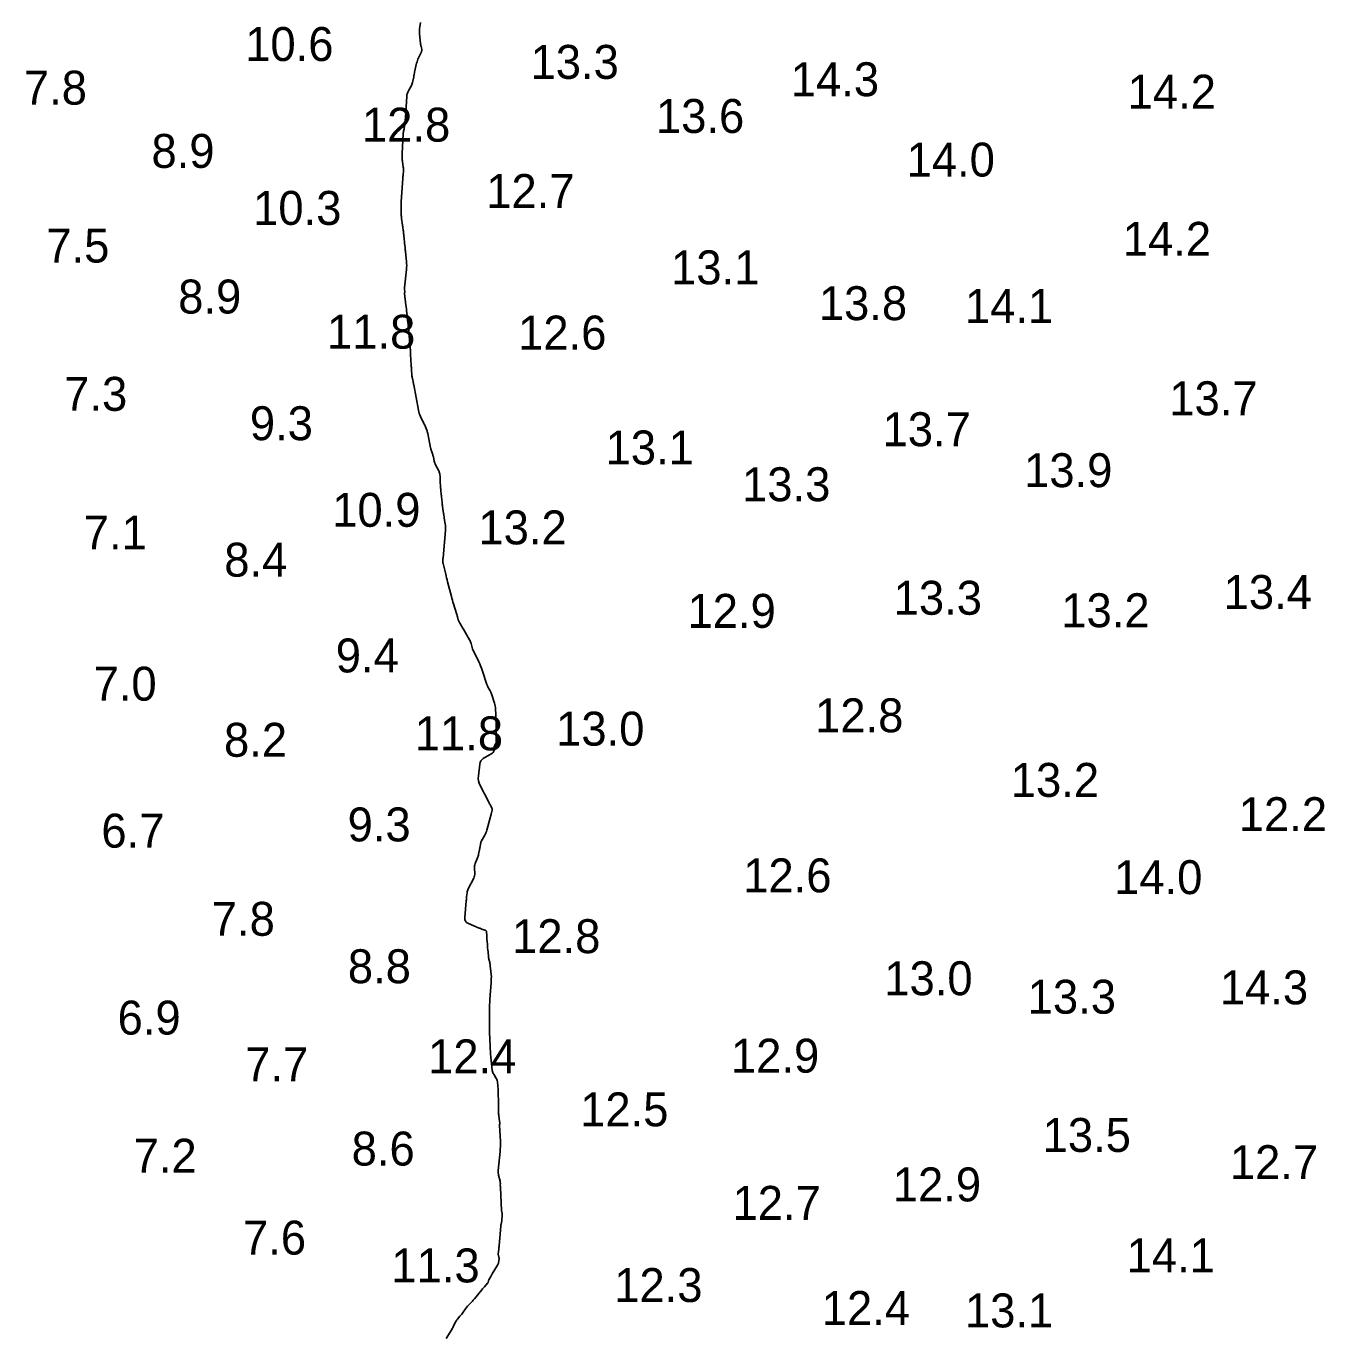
# Model space of a CAD drawing. Extents: x 815352 to 820877, y 582403 to 597439.
# Drawn here: x 820452.6 to 820644, y 590619.8 to 590813 of the extents above; entities that cross this region are included whole.
import ezdxf

# ---------------------------------------------------------------- set-up
doc = ezdxf.new("R2010")
doc.units = 0
doc.layers.add('V-CONT-EL12', color=7, linetype='Continuous')
doc.layers.add('V-TOPO-SOUN', color=7, linetype='Continuous')

msp = doc.modelspace()

# ---------------------------------------------------------------- linework, layer by layer
at = {"layer": 'V-CONT-EL12'}
msp.add_lwpolyline([(820514.49, 590619.55), (820515.32, 590620.92), (820515.39, 590621.05), (820515.46, 590621.17), (820515.53, 590621.3), (820515.59, 590621.44), (820515.85, 590621.98), (820515.91, 590622.1), (820515.99, 590622.22), (820516.07, 590622.33), (820516.15, 590622.44), (820516.52, 590622.86), (820516.62, 590622.97), (820516.7, 590623.07), (820516.79, 590623.18), (820516.87, 590623.3), (820517.43, 590624.08), (820517.53, 590624.2), (820517.62, 590624.32), (820517.73, 590624.44), (820517.83, 590624.54), (820518.27, 590624.98), (820518.38, 590625.08), (820518.48, 590625.2), (820518.58, 590625.31), (820518.68, 590625.43), (820519.76, 590626.76), (820519.85, 590626.87), (820519.94, 590626.97), (820520.03, 590627.07), (820520.12, 590627.17), (820520.6, 590627.71), (820520.63, 590627.74), (820520.65, 590627.78), (820520.67, 590627.83), (820520.68, 590627.87), (820520.73, 590628.06), (820520.74, 590628.1), (820520.76, 590628.15), (820520.77, 590628.19), (820520.79, 590628.23), (820521.05, 590628.72), (820521.1, 590628.81), (820521.15, 590628.91), (820521.2, 590629), (820521.26, 590629.09), (820522.07, 590630.39), (820522.12, 590630.49), (820522.16, 590630.58), (820522.19, 590630.69), (820522.21, 590630.79), (820522.28, 590631.31), (820522.28, 590631.37), (820522.28, 590631.43), (820522.27, 590631.49), (820522.26, 590631.55), (820522.19, 590631.79), (820522.18, 590631.85), (820522.17, 590631.91), (820522.17, 590631.97), (820522.17, 590632.03), (820522.24, 590632.73), (820522.26, 590632.87), (820522.27, 590633), (820522.28, 590633.14), (820522.29, 590633.28), (820522.52, 590636.12), (820522.53, 590636.19), (820522.54, 590636.26), (820522.55, 590636.33), (820522.57, 590636.4), (820522.64, 590636.69), (820522.66, 590636.76), (820522.68, 590636.83), (820522.69, 590636.9), (820522.69, 590636.98), (820522.75, 590637.79), (820522.75, 590637.85), (820522.75, 590637.9), (820522.74, 590637.95), (820522.73, 590638.01), (820522.68, 590638.22), (820522.67, 590638.27), (820522.66, 590638.33), (820522.65, 590638.38), (820522.65, 590638.43), (820522.47, 590641.82), (820522.47, 590641.9), (820522.47, 590641.98), (820522.46, 590642.05), (820522.46, 590642.13), (820522.47, 590642.44), (820522.46, 590642.52), (820522.46, 590642.59), (820522.45, 590642.67), (820522.43, 590642.75), (820522.22, 590643.63), (820522.19, 590643.81), (820522.17, 590643.98), (820522.16, 590644.16), (820522.17, 590644.33), (820522.43, 590647.11), (820522.46, 590647.5), (820522.47, 590647.89), (820522.48, 590648.28), (820522.47, 590648.67), (820522.37, 590650.96), (820522.37, 590650.99), (820522.37, 590651.02), (820522.37, 590651.05), (820522.37, 590651.08), (820522.38, 590651.19), (820522.38, 590651.22), (820522.38, 590651.25), (820522.38, 590651.28), (820522.38, 590651.31), (820522.25, 590652.35), (820522.23, 590652.48), (820522.22, 590652.62), (820522.22, 590652.76), (820522.21, 590652.9), (820522.22, 590653.45), (820522.22, 590653.58), (820522.22, 590653.72), (820522.21, 590653.86), (820522.21, 590654), (820522.14, 590656.17), (820522.14, 590656.32), (820522.13, 590656.48), (820522.11, 590656.64), (820522.1, 590656.79), (820522.03, 590657.42), (820522, 590657.57), (820521.96, 590657.72), (820521.9, 590657.86), (820521.82, 590657.99), (820521.49, 590658.51), (820521.41, 590658.65), (820521.35, 590658.79), (820521.31, 590658.93), (820521.28, 590659.09), (820521.07, 590661.09), (820521.03, 590661.47), (820521, 590661.86), (820520.98, 590662.25), (820520.96, 590662.63), (820520.89, 590664.74), (820520.88, 590665.14), (820520.87, 590665.54), (820520.86, 590665.94), (820520.86, 590666.34), (820520.87, 590667.93), (820520.87, 590668.33), (820520.89, 590668.73), (820520.91, 590669.13), (820520.93, 590669.53), (820521.13, 590672.04), (820521.13, 590672.11), (820521.13, 590672.17), (820521.13, 590672.23), (820521.13, 590672.29), (820521.11, 590672.64), (820521.11, 590672.66), (820521.11, 590672.67), (820521.12, 590672.69), (820521.12, 590672.7), (820521.14, 590672.76), (820521.15, 590672.77), (820521.15, 590672.79), (820521.15, 590672.8), (820521.15, 590672.82), (820520.98, 590674.49), (820520.97, 590674.61), (820520.95, 590674.74), (820520.93, 590674.86), (820520.9, 590674.98), (820520.79, 590675.46), (820520.77, 590675.59), (820520.75, 590675.71), (820520.73, 590675.83), (820520.72, 590675.95), (820520.62, 590676.9), (820520.6, 590677.08), (820520.59, 590677.27), (820520.57, 590677.45), (820520.56, 590677.63), (820520.5, 590678.48), (820520.49, 590678.61), (820520.48, 590678.73), (820520.47, 590678.85), (820520.46, 590678.97), (820520.43, 590679.48), (820520.41, 590679.58), (820520.36, 590679.66), (820520.29, 590679.73), (820520.19, 590679.77), (820519.76, 590679.9), (820519.65, 590679.94), (820519.54, 590679.98), (820519.44, 590680.02), (820519.33, 590680.06), (820517.76, 590680.72), (820517.5, 590680.86), (820517.32, 590681.06), (820517.23, 590681.31), (820517.22, 590681.61), (820517.45, 590684.08), (820517.46, 590684.23), (820517.47, 590684.38), (820517.49, 590684.53), (820517.5, 590684.67), (820517.57, 590685.27), (820517.59, 590685.41), (820517.62, 590685.56), (820517.67, 590685.69), (820517.73, 590685.83), (820518.54, 590687.43), (820518.61, 590687.59), (820518.66, 590687.76), (820518.69, 590687.94), (820518.69, 590688.12), (820518.66, 590688.85), (820518.66, 590689.03), (820518.68, 590689.21), (820518.72, 590689.39), (820518.78, 590689.56), (820519.11, 590690.39), (820519.16, 590690.53), (820519.2, 590690.67), (820519.24, 590690.8), (820519.27, 590690.95), (820519.4, 590691.57), (820519.42, 590691.68), (820519.44, 590691.8), (820519.46, 590691.91), (820519.48, 590692.02), (820519.55, 590692.48), (820519.58, 590692.59), (820519.61, 590692.7), (820519.65, 590692.8), (820519.7, 590692.9), (820520.18, 590693.75), (820520.27, 590693.93), (820520.35, 590694.11), (820520.42, 590694.3), (820520.48, 590694.49), (820520.96, 590696.3), (820520.97, 590696.32), (820520.97, 590696.34), (820520.98, 590696.35), (820520.98, 590696.37), (820521, 590696.44), (820521.01, 590696.45), (820521.01, 590696.47), (820521.02, 590696.49), (820521.02, 590696.5), (820521.11, 590696.8), (820521.12, 590696.86), (820521.14, 590696.92), (820521.15, 590696.97), (820521.17, 590697.03), (820521.27, 590697.42), (820521.28, 590697.5), (820521.28, 590697.58), (820521.26, 590697.66), (820521.23, 590697.74), (820520.95, 590698.26), (820520.89, 590698.37), (820520.83, 590698.49), (820520.78, 590698.6), (820520.72, 590698.71), (820519.49, 590701.07), (820519.35, 590701.41), (820519.25, 590701.76), (820519.22, 590702.12), (820519.23, 590702.49), (820519.43, 590704.22), (820519.48, 590704.47), (820519.59, 590704.69), (820519.74, 590704.87), (820519.95, 590705.03), (820521.23, 590705.79), (820521.27, 590705.82), (820521.32, 590705.85), (820521.36, 590705.89), (820521.39, 590705.94), (820521.53, 590706.12), (820521.56, 590706.17), (820521.58, 590706.22), (820521.59, 590706.27), (820521.59, 590706.33), (820521.57, 590706.77), (820521.58, 590706.83), (820521.59, 590706.9), (820521.61, 590706.96), (820521.64, 590707.02), (820521.8, 590707.25), (820521.83, 590707.31), (820521.85, 590707.37), (820521.87, 590707.44), (820521.87, 590707.5), (820521.84, 590710.69), (820521.84, 590710.9), (820521.83, 590711.11), (820521.83, 590711.32), (820521.81, 590711.53), (820521.76, 590712.36), (820521.75, 590712.57), (820521.71, 590712.77), (820521.67, 590712.98), (820521.61, 590713.18), (820521.16, 590714.55), (820521.11, 590714.67), (820521.06, 590714.8), (820521.01, 590714.91), (820520.95, 590715.03), (820520.69, 590715.49), (820520.63, 590715.61), (820520.57, 590715.73), (820520.52, 590715.85), (820520.48, 590715.97), (820519.79, 590718.06), (820519.68, 590718.37), (820519.56, 590718.68), (820519.43, 590718.99), (820519.29, 590719.29), (820518.55, 590720.8), (820518.49, 590720.94), (820518.43, 590721.08), (820518.38, 590721.23), (820518.34, 590721.38), (820518.17, 590721.97), (820518.12, 590722.11), (820518.07, 590722.25), (820518, 590722.39), (820517.93, 590722.53), (820517.08, 590724.01), (820517, 590724.14), (820516.93, 590724.26), (820516.86, 590724.39), (820516.78, 590724.52), (820516.45, 590725.07), (820516.4, 590725.17), (820516.35, 590725.28), (820516.31, 590725.39), (820516.28, 590725.5), (820516.15, 590725.94), (820516.12, 590726.05), (820516.09, 590726.17), (820516.05, 590726.28), (820516.02, 590726.39), (820515.57, 590727.82), (820515.48, 590728.1), (820515.4, 590728.37), (820515.32, 590728.65), (820515.25, 590728.93), (820514.7, 590731.08), (820514.63, 590731.37), (820514.56, 590731.65), (820514.49, 590731.94), (820514.42, 590732.22), (820514.03, 590733.8), (820514.02, 590733.86), (820514.01, 590733.93), (820514, 590734), (820514, 590734.07), (820514.01, 590734.35), (820514.02, 590734.42), (820514.02, 590734.49), (820514.03, 590734.56), (820514.03, 590734.63), (820514.37, 590738.65), (820514.37, 590738.7), (820514.38, 590738.76), (820514.38, 590738.81), (820514.39, 590738.86), (820514.4, 590739.09), (820514.4, 590739.13), (820514.4, 590739.18), (820514.4, 590739.22), (820514.4, 590739.26), (820514.37, 590739.43), (820514.37, 590739.47), (820514.36, 590739.51), (820514.36, 590739.55), (820514.35, 590739.59), (820514.21, 590740.5), (820514.19, 590740.67), (820514.16, 590740.83), (820514.14, 590741), (820514.11, 590741.16), (820513.97, 590742.16), (820513.94, 590742.33), (820513.92, 590742.49), (820513.9, 590742.65), (820513.88, 590742.82), (820513.8, 590743.59), (820513.79, 590743.7), (820513.78, 590743.81), (820513.76, 590743.92), (820513.75, 590744.03), (820513.71, 590744.46), (820513.7, 590744.57), (820513.69, 590744.68), (820513.68, 590744.79), (820513.67, 590744.9), (820513.61, 590746.04), (820513.61, 590746.16), (820513.6, 590746.28), (820513.59, 590746.4), (820513.58, 590746.52), (820513.53, 590746.99), (820513.51, 590747.11), (820513.48, 590747.23), (820513.44, 590747.34), (820513.4, 590747.44), (820512.94, 590748.33), (820512.88, 590748.46), (820512.83, 590748.59), (820512.78, 590748.73), (820512.74, 590748.87), (820512.6, 590749.49), (820512.57, 590749.61), (820512.54, 590749.72), (820512.51, 590749.83), (820512.47, 590749.94), (820512.32, 590750.39), (820512.28, 590750.5), (820512.25, 590750.61), (820512.22, 590750.72), (820512.2, 590750.84), (820511.77, 590752.94), (820511.74, 590753.07), (820511.71, 590753.2), (820511.67, 590753.32), (820511.62, 590753.44), (820511.42, 590753.93), (820511.37, 590754.05), (820511.32, 590754.17), (820511.26, 590754.29), (820511.21, 590754.41), (820510.7, 590755.46), (820510.6, 590755.68), (820510.52, 590755.9), (820510.45, 590756.13), (820510.4, 590756.36), (820509.7, 590760.11), (820509.68, 590760.23), (820509.66, 590760.35), (820509.63, 590760.47), (820509.61, 590760.59), (820509.51, 590761.06), (820509.48, 590761.18), (820509.46, 590761.3), (820509.45, 590761.42), (820509.44, 590761.55), (820509.38, 590762.31), (820509.37, 590762.48), (820509.36, 590762.65), (820509.35, 590762.82), (820509.34, 590762.99), (820509.25, 590764.59), (820509.25, 590764.67), (820509.24, 590764.74), (820509.24, 590764.81), (820509.23, 590764.89), (820509.22, 590765.19), (820509.21, 590765.26), (820509.21, 590765.34), (820509.2, 590765.41), (820509.2, 590765.49), (820509.17, 590765.83), (820509.17, 590765.91), (820509.16, 590765.99), (820509.15, 590766.07), (820509.15, 590766.15), (820508.93, 590768.54), (820508.92, 590768.6), (820508.92, 590768.65), (820508.91, 590768.71), (820508.91, 590768.76), (820508.89, 590768.98), (820508.88, 590769.04), (820508.87, 590769.09), (820508.87, 590769.15), (820508.86, 590769.21), (820508.68, 590770.76), (820508.65, 590771.03), (820508.62, 590771.31), (820508.59, 590771.59), (820508.56, 590771.86), (820508.37, 590773.55), (820508.36, 590773.57), (820508.36, 590773.6), (820508.37, 590773.62), (820508.37, 590773.65), (820508.38, 590773.75), (820508.39, 590773.78), (820508.39, 590773.8), (820508.39, 590773.83), (820508.39, 590773.85), (820508.36, 590774.15), (820508.36, 590774.21), (820508.36, 590774.26), (820508.36, 590774.32), (820508.36, 590774.38), (820508.64, 590777.11), (820508.66, 590777.4), (820508.67, 590777.69), (820508.66, 590777.98), (820508.64, 590778.27), (820508.5, 590779.71), (820508.49, 590779.87), (820508.47, 590780.02), (820508.45, 590780.18), (820508.44, 590780.34), (820508.36, 590780.98), (820508.35, 590781.14), (820508.33, 590781.3), (820508.31, 590781.46), (820508.29, 590781.61), (820508.2, 590782.56), (820508.19, 590782.65), (820508.18, 590782.74), (820508.16, 590782.83), (820508.15, 590782.92), (820508.1, 590783.28), (820508.09, 590783.37), (820508.08, 590783.46), (820508.07, 590783.56), (820508.06, 590783.65), (820507.93, 590784.61), (820507.91, 590784.76), (820507.89, 590784.92), (820507.88, 590785.07), (820507.88, 590785.23), (820507.86, 590785.95), (820507.86, 590786.05), (820507.85, 590786.15), (820507.85, 590786.25), (820507.85, 590786.35), (820507.85, 590786.75), (820507.85, 590786.85), (820507.86, 590786.95), (820507.86, 590787.05), (820507.87, 590787.15), (820508.1, 590790.52), (820508.11, 590790.66), (820508.12, 590790.8), (820508.13, 590790.94), (820508.14, 590791.08), (820508.19, 590791.63), (820508.2, 590791.77), (820508.2, 590791.91), (820508.19, 590792.05), (820508.17, 590792.19), (820508.04, 590793.04), (820508.03, 590793.13), (820508.02, 590793.22), (820508.01, 590793.31), (820508, 590793.4), (820507.98, 590793.76), (820507.98, 590793.86), (820507.98, 590793.95), (820507.98, 590794.04), (820507.99, 590794.13), (820508.16, 590797.17), (820508.17, 590797.25), (820508.18, 590797.33), (820508.19, 590797.41), (820508.2, 590797.48), (820508.28, 590797.79), (820508.29, 590797.86), (820508.31, 590797.94), (820508.32, 590798.02), (820508.33, 590798.1), (820508.43, 590798.91), (820508.45, 590799.07), (820508.47, 590799.23), (820508.48, 590799.39), (820508.49, 590799.55), (820508.67, 590802.61), (820508.68, 590802.69), (820508.69, 590802.77), (820508.71, 590802.85), (820508.73, 590802.92), (820508.84, 590803.22), (820508.87, 590803.3), (820508.9, 590803.37), (820508.93, 590803.44), (820508.97, 590803.51), (820509.37, 590804.23), (820509.44, 590804.38), (820509.5, 590804.53), (820509.55, 590804.68), (820509.58, 590804.84), (820509.7, 590805.52), (820509.73, 590805.69), (820509.76, 590805.86), (820509.8, 590806.02), (820509.84, 590806.19), (820510.14, 590807.51), (820510.19, 590807.7), (820510.25, 590807.9), (820510.32, 590808.09), (820510.4, 590808.28), (820510.84, 590809.2), (820510.87, 590809.3), (820510.89, 590809.39), (820510.89, 590809.49), (820510.88, 590809.59), (820510.78, 590809.99), (820510.76, 590810.09), (820510.74, 590810.19), (820510.72, 590810.29), (820510.71, 590810.39), (820510.56, 590811.81), (820510.55, 590812.01), (820510.55, 590812.2), (820510.56, 590812.4), (820510.58, 590812.59), (820510.7, 590813.48)], dxfattribs=at)

# ---------------------------------------------------------------- texts
at = {"layer": 'V-TOPO-SOUN'}
for s, p in [('10.6 ', (820484.87, 590807.83)), ('13.3 ', (820526.92, 590805.2)), ('14.3 ', (820565.27, 590802.64)), ('7.8', (820452.26, 590801.4)), ('14.2 ', (820614.91, 590800.81)), ('13.6 ', (820545.4, 590797.23)), ('12.8 ', (820502.08, 590795.95)), ('8.9', (820471.06, 590792.08)), ('14.0 ', (820582.33, 590790.8)), ('12.7 ', (820520.39, 590786.17)), ('10.3 ', (820486.04, 590783.68)), ('7.5', (820455.57, 590778.13)), ('14.2 ', (820614.19, 590779.12)), ('13.1 ', (820547.63, 590774.92)), ('8.9', (820475, 590770.62)), ('13.8 ', (820569.4, 590769.64)), ('14.1 ', (820590.93, 590769.24)), ('11.8 ', (820496.93, 590765.44)), ('12.6 ', (820525.09, 590765.31)), ('7.3', (820458.2, 590756.28)), ('13.7 ', (820621.05, 590755.63)), ('9.3', (820485.56, 590751.95)), ('13.7 ', (820578.79, 590751.07)), ('13.1 ', (820537.98, 590748.38)), ('13.9 ', (820599.65, 590745.03)), ('13.3 ', (820558.09, 590742.96)), ('10.9 ', (820497.69, 590739.19)), ('7.1', (820461.09, 590735.85)), ('13.2 ', (820519.24, 590736.6)), ('8.4', (820481.79, 590731.84)), ('13.4 ', (820629.05, 590727.09)), ('13.3 ', (820580.43, 590726.23)), ('12.9 ', (820550.05, 590724.3)), ('13.2 ', (820605.13, 590724.39)), ('9.4', (820498.22, 590717.73)), ('7.0', (820462.53, 590713.57)), ('12.8 ', (820568.85, 590708.91)), ('11.8 ', (820509.86, 590706.25)), ('13.0 ', (820530.69, 590706.94)), ('8.2', (820481.75, 590705.3)), ('13.2 ', (820597.69, 590699.39)), ('12.2 ', (820631.28, 590694.34)), ('9.3', (820499.96, 590692.83)), ('6.7', (820463.68, 590691.91)), ('12.6 ', (820558.26, 590685.32)), ('14.0 ', (820612.91, 590685.06)), ('7.8', (820479.95, 590678.92)), ('12.8 ', (820524.2, 590676.36)), ('8.8', (820500, 590671.93)), ('13.0 ', (820579.05, 590670.16)), ('13.3 ', (820600.18, 590667.44)), ('14.3 ', (820628.49, 590668.82)), ('6.9', (820466.07, 590664.36)), ('12.4 ', (820511.83, 590658.65)), ('12.9 ', (820556.45, 590658.75)), ('7.7', (820484.87, 590657.47)), ('12.5 ', (820534.23, 590650.84)), ('13.5 ', (820602.38, 590647.07)), ('7.2', (820468.43, 590644.01)), ('8.6', (820500.56, 590645.06)), ('12.7 ', (820629.97, 590643.06)), ('12.9 ', (820580.3, 590639.78)), ('12.7 ', (820556.68, 590637.06)), ('7.6', (820484.55, 590631.94)), ('14.1 ', (820614.75, 590629.32)), ('11.3 ', (820506.41, 590627.84)), ('12.3 ', (820539.25, 590624.95)), ('12.4 ', (820569.83, 590621.57)), ('13.1 ', (820590.93, 590621.21))]:
    msp.add_text(s, height=5, dxfattribs=at).set_placement(p)

doc.saveas('drawing.dxf')
